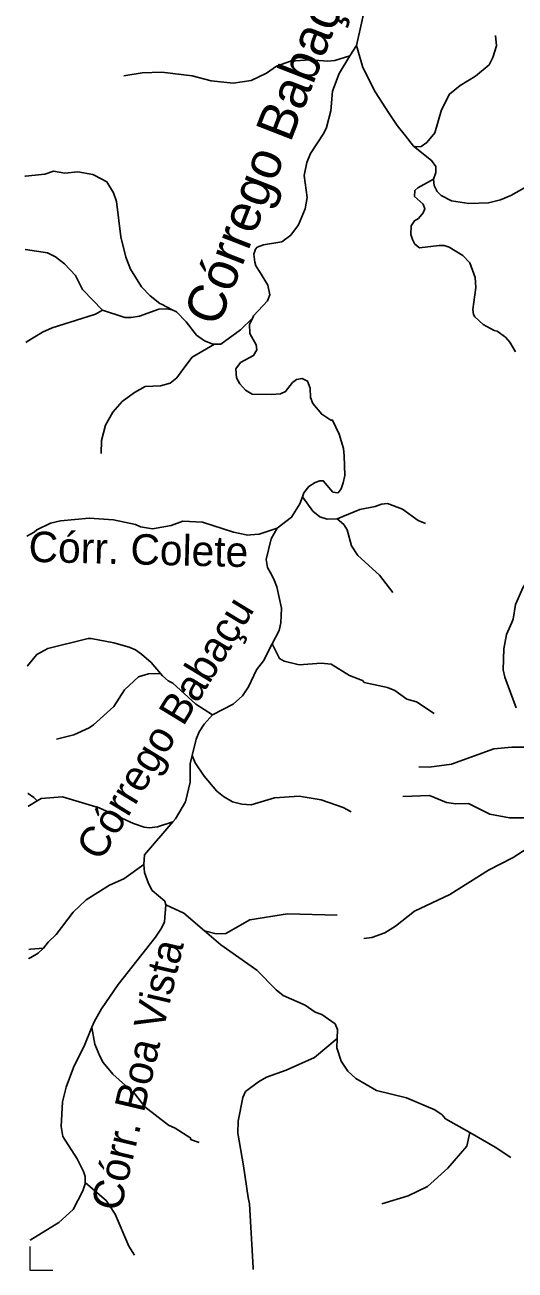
# Model space of a CAD drawing. Extents: x 393 to 446.6, y 8175.5 to 8231.
# Drawn here: x 393.24 to 395.81, y 8175.47 to 8182.01 of the extents above; entities that cross this region are included whole.
import ezdxf
from ezdxf.enums import TextEntityAlignment as Align

# ---------------------------------------------------------------- set-up
doc = ezdxf.new("R2010")
doc.units = 0
doc.header["$LTSCALE"] = 0.064
doc.linetypes.add('LONG_DASHED', pattern=[7.5, 6, -1.5])
doc.layers.add('61', color=7, linetype='Continuous')
for name, color, linetype, lineweight in [('63', 7, 'Continuous', 13), ('7', 7, 'Continuous', 25), ('9', 7, 'LONG_DASHED', 25)]:
    doc.layers.add(name, color=color, linetype=linetype, lineweight=lineweight)

msp = doc.modelspace()

# ---------------------------------------------------------------- linework, layer by layer
at = {"layer": '63'}
msp.add_lwpolyline([(393.2669, 8175.5946), (393.2669, 8175.4714), (393.3883, 8175.4714)], dxfattribs=at)
at = {"layer": '7'}
msp.add_line((394.948, 8181.8527), (394.9815, 8181.9071), dxfattribs=at)
for points in [[(394.9815, 8181.9071), (395.0342, 8182.1402)], [(395.7128, 8181.9584), (395.7172, 8181.9044), (395.6979, 8181.843), (395.6785, 8181.8043), (395.6075, 8181.7445), (395.5267, 8181.696), (395.4702, 8181.6509), (395.4282, 8181.5685), (395.3943, 8181.4474), (395.3523, 8181.3973), (395.3216, 8181.3763), (395.299, 8181.3731), (395.2815, 8181.378)], [(395.2815, 8181.378), (395.2394, 8181.4311), (395.1957, 8181.4861), (395.1537, 8181.5491), (395.081, 8181.6622), (395.0148, 8181.7914), (394.9815, 8181.9071)], [(393.7599, 8181.7473), (393.857, 8181.7623), (393.9604, 8181.7655), (394.1186, 8181.7461), (394.2187, 8181.7203), (394.335, 8181.709), (394.4287, 8181.7219), (394.5094, 8181.7606), (394.5627, 8181.7978), (394.6354, 8181.8236), (394.7387, 8181.8301), (394.831, 8181.8233), (394.8683, 8181.8279), (394.948, 8181.8527)], [(394.4371, 8180.4757), (394.4416, 8180.4849), (394.5142, 8180.5641), (394.5271, 8180.5964), (394.5174, 8180.6464), (394.4762, 8180.7131), (394.4545, 8180.7482), (394.448, 8180.7676), (394.4432, 8180.8095), (394.4528, 8180.8354), (394.461, 8180.8467), (394.4933, 8180.858), (394.5902, 8180.8741), (394.6369, 8180.9096), (394.6773, 8180.9646), (394.7128, 8181.0485), (394.7241, 8181.1067), (394.708, 8181.2229), (394.7209, 8181.2908), (394.7403, 8181.3392), (394.8113, 8181.4458), (394.8243, 8181.4748), (394.8469, 8181.5621), (394.8565, 8181.6654), (394.8905, 8181.7591), (394.948, 8181.8527)], [(396.9003, 8181.7475), (396.9061, 8181.7102), (396.9009, 8181.6686), (396.8427, 8181.5394), (396.8137, 8181.4975), (396.7523, 8181.4409), (396.6377, 8181.3698), (396.5521, 8181.3053), (396.4762, 8181.2827), (396.36, 8181.2681), (396.1791, 8181.2681), (396.1016, 8181.2584), (396.0112, 8181.2326), (395.9078, 8181.1825), (395.8495, 8181.1496), (395.7932, 8181.1179), (395.7383, 8181.0953), (395.6753, 8181.0792), (395.5719, 8181.076), (395.4815, 8181.0905), (395.4266, 8181.1179), (395.4056, 8181.1389), (395.3894, 8181.1713), (395.3864, 8181.2035)], [(395.3864, 8181.2035), (395.3991, 8181.2391), (395.3991, 8181.2698), (395.3765, 8181.3021), (395.2815, 8181.378)], [(395.8174, 8180.2961), (395.7867, 8180.3477), (395.7641, 8180.3736), (395.7205, 8180.4058), (395.7044, 8180.4091), (395.6478, 8180.4397), (395.6042, 8180.4801), (395.5961, 8180.4931), (395.5929, 8180.5189), (395.609, 8180.6352), (395.6058, 8180.6868), (395.5767, 8180.7643), (395.5412, 8180.8031), (395.4686, 8180.8467), (395.4428, 8180.8547), (395.4169, 8180.8547), (395.3136, 8180.8434), (395.2893, 8180.8628), (395.2764, 8180.8871), (395.2683, 8180.9129), (395.2699, 8180.9581), (395.2877, 8180.9856), (395.3071, 8180.9968), (395.3329, 8181.0275), (395.341, 8181.0485), (395.3329, 8181.0728), (395.2877, 8181.1131), (395.2893, 8181.1438), (395.3039, 8181.1583), (395.3864, 8181.2035)], [(394.6986, 8179.5348), (394.7064, 8179.5565), (394.7322, 8179.5888), (394.7645, 8179.6097), (394.7894, 8179.6195), (394.8081, 8179.6194), (394.8582, 8179.5597), (394.8856, 8179.5548), (394.9018, 8179.5759), (394.9115, 8179.6082), (394.9211, 8179.6469), (394.9179, 8179.7503), (394.9147, 8179.789), (394.8921, 8179.8633), (394.8566, 8179.9375), (394.8469, 8179.9375), (394.8, 8179.9682), (394.7532, 8180.0248), (394.7403, 8180.0571), (394.7387, 8180.1055), (394.7258, 8180.1426), (394.6967, 8180.1572), (394.6676, 8180.1507), (394.6466, 8180.1362), (394.6095, 8180.0877), (394.5837, 8180.0764), (394.5352, 8180.0716), (394.4351, 8180.0748), (394.3996, 8180.0958), (394.3689, 8180.1281), (394.3527, 8180.1604), (394.3495, 8180.2072), (394.3737, 8180.2412), (394.4416, 8180.2766), (394.4593, 8180.3073), (394.4561, 8180.3332), (394.4222, 8180.3929), (394.4201, 8180.4411), (394.4371, 8180.4757)], [(395.82, 8178.4259), (395.7608, 8178.5876), (395.7528, 8178.6264), (395.756, 8178.7362), (395.7705, 8178.812), (395.7971, 8178.8741), (395.8044, 8178.8912), (395.8174, 8178.9687), (395.8577, 8179.0591), (395.8981, 8179.1173), (395.9449, 8179.1657), (395.9869, 8179.2529), (396.0402, 8179.3191), (396.0596, 8179.3595), (396.0725, 8179.4111), (396.0693, 8179.4596), (396.0031, 8179.6534), (396.0106, 8179.8498)], [(394.5662, 8179.3694), (394.6418, 8179.4273), (394.6854, 8179.4983), (394.6986, 8179.5348)], [(394.88, 8179.4192), (394.8291, 8179.4176), (394.7904, 8179.4289), (394.7532, 8179.4596), (394.699, 8179.5342), (394.6986, 8179.5348)], [(395.3448, 8179.3938), (395.3055, 8179.4111), (395.2231, 8179.4693), (395.1456, 8179.4999), (395.1133, 8179.4967), (395.081, 8179.4838), (395.0003, 8179.4676), (394.88, 8179.4192)], [(395.1738, 8179.0319), (395.1037, 8179.1237), (394.989, 8179.227), (394.9567, 8179.2771), (394.9341, 8179.3611), (394.9163, 8179.3885), (394.88, 8179.4192)], [(394.5395, 8178.7616), (394.5756, 8178.8331), (394.5853, 8178.8718), (394.5885, 8178.9493), (394.5643, 8179.0624), (394.551, 8179.0936), (394.5368, 8179.1269), (394.5142, 8179.1641), (394.5078, 8179.2045), (394.5336, 8179.3143), (394.5662, 8179.3694)], [(393.2538, 8178.6461), (393.2541, 8178.6463), (393.3031, 8178.7055), (393.3612, 8178.7377), (393.5728, 8178.7894), (393.589, 8178.791), (393.7085, 8178.7668), (393.7892, 8178.7442), (393.8215, 8178.7313), (393.8538, 8178.7071), (393.9038, 8178.6635), (393.9524, 8178.6071)], [(394.2267, 8178.3897), (394.335, 8178.4455), (394.3834, 8178.4891), (394.4157, 8178.5359), (394.4577, 8178.6264), (394.4948, 8178.6732), (394.5395, 8178.7616)], [(395.3898, 8178.3966), (395.2974, 8178.4568), (395.2458, 8178.4713), (395.1828, 8178.5165), (395.1456, 8178.5327), (395.0229, 8178.5585), (395.0132, 8178.5698), (394.9454, 8178.5956), (394.8501, 8178.6554), (394.7968, 8178.6603), (394.6806, 8178.6522), (394.6031, 8178.6715), (394.5788, 8178.6845), (394.5395, 8178.7616)], [(393.4067, 8178.2617), (393.4985, 8178.284), (393.5793, 8178.3211), (393.6019, 8178.3373), (393.7084, 8178.4326), (393.7649, 8178.5198), (393.8377, 8178.5892), (393.8893, 8178.6037), (393.9507, 8178.607), (393.9524, 8178.6071)], [(393.9524, 8178.6071), (393.9636, 8178.5941), (393.9926, 8178.5682), (394.0185, 8178.5553), (394.138, 8178.4455), (394.2267, 8178.3897)], [(394.1191, 8178.1751), (394.1396, 8178.2614), (394.1557, 8178.3002), (394.1816, 8178.3405), (394.2267, 8178.3897)], [(395.3098, 8178.1161), (395.3645, 8178.1149), (395.4815, 8178.1306), (395.7027, 8178.2097), (395.798, 8178.2194), (395.8788, 8178.2194), (395.9304, 8178.2275), (396.0338, 8178.2275), (396.0984, 8178.2145), (396.1759, 8178.2145), (396.2227, 8178.221), (396.2517, 8178.242), (396.3052, 8178.2611)], [(394.0179, 8177.8274), (394.0314, 8177.8432), (394.0847, 8177.932), (394.1089, 8178.0353), (394.1089, 8178.1322), (394.1191, 8178.1751)], [(394.9541, 8177.8802), (394.9115, 8177.9029), (394.7968, 8177.9417), (394.6806, 8177.961), (394.5514, 8177.9529), (394.4287, 8177.9158), (394.3802, 8177.919), (394.3318, 8177.932), (394.2833, 8177.9594), (394.2494, 8177.9885), (394.1832, 8178.0676), (394.1347, 8178.1371), (394.1191, 8178.1751)], [(393.2572, 8177.9751), (393.2574, 8177.975), (393.2878, 8177.9553), (393.3063, 8177.937)], [(395.2251, 8177.9607), (395.3653, 8177.9659), (395.4557, 8177.9287), (395.5041, 8177.9223), (395.5703, 8177.9239), (395.6818, 8177.8674), (395.7851, 8177.848), (395.8594, 8177.848), (395.9886, 8177.8609), (396.1406, 8177.8996)], [(393.2575, 8177.9085), (393.2577, 8177.9086), (393.2656, 8177.9132), (393.3063, 8177.937)], [(393.3063, 8177.937), (393.3273, 8177.9493), (393.4388, 8177.9578), (393.631, 8177.8997), (393.8118, 8177.8183), (393.8677, 8177.7997), (393.8957, 8177.7956), (393.9365, 8177.8014), (394.0179, 8177.8274)], [(395.0202, 8177.2137), (395.0621, 8177.2184), (395.1311, 8177.2441), (395.1876, 8177.278), (395.2877, 8177.3571), (395.4718, 8177.4459), (395.6753, 8177.5735), (395.8045, 8177.6397), (395.9223, 8177.7156), (396.0903, 8177.8464), (396.1406, 8177.8996)], [(393.8649, 8177.6019), (393.8699, 8177.6542), (394.0179, 8177.8274)], [(393.3381, 8177.1623), (393.3625, 8177.1949), (393.4049, 8177.2344), (393.4937, 8177.3523), (393.5631, 8177.4168), (393.6859, 8177.4943), (393.7601, 8177.5266), (393.8649, 8177.6019)], [(393.9809, 8177.3907), (393.9751, 8177.4093), (393.9087, 8177.4669), (393.8893, 8177.5025), (393.8683, 8177.5606), (393.8649, 8177.6019)], [(393.5932, 8176.7478), (393.6062, 8176.7791), (393.6438, 8176.8436), (393.731, 8176.9728), (393.9264, 8177.2215), (393.9587, 8177.2683), (393.9733, 8177.3022), (393.9809, 8177.3907)], [(393.2612, 8177.1566), (393.2614, 8177.1566), (393.2712, 8177.1573), (393.3381, 8177.1623)], [(393.2615, 8177.1078), (393.2616, 8177.1079), (393.2729, 8177.1146), (393.3101, 8177.1367), (393.3381, 8177.1623)], [(393.5581, 8175.9319), (393.557, 8175.9628), (393.5489, 8175.9896), (393.5163, 8176.0556), (393.4404, 8176.1734), (393.4323, 8176.2268), (393.4388, 8176.356), (393.4581, 8176.4335), (393.4969, 8176.5368), (393.555, 8176.6563), (393.5932, 8176.7478)], [(394.1568, 8176.1421), (394.1114, 8176.1584), (394.1121, 8176.1638), (394.0298, 8176.2171), (393.9943, 8176.2332), (393.8715, 8176.3285), (393.8182, 8176.3979), (393.702, 8176.5013), (393.6519, 8176.5626), (393.6342, 8176.5949), (393.6091, 8176.6594), (393.5934, 8176.7465), (393.5932, 8176.7478)], [(393.2688, 8175.6294), (393.2688, 8175.6295), (393.4194, 8175.7213), (393.4937, 8175.7891), (393.5453, 8175.8877), (393.5583, 8175.9248), (393.5581, 8175.9319)], [(393.8165, 8175.5493), (393.786, 8175.597), (393.7149, 8175.7649), (393.6858, 8175.8101), (393.6676, 8175.8365), (393.5593, 8175.9308), (393.5581, 8175.9319)]]:
    msp.add_lwpolyline(points, dxfattribs=at)
at = {"layer": '9'}
for points in [[(393.2412, 8181.2202), (393.2415, 8181.2202), (393.2435, 8181.2204), (393.3451, 8181.2294), (393.392, 8181.2455), (393.4501, 8181.2358), (393.5195, 8181.2423), (393.5986, 8181.2277), (393.6088, 8181.2223), (393.6713, 8181.189), (393.7068, 8181.1325), (393.7214, 8181.0873), (393.744, 8180.9016), (393.7714, 8180.7934), (393.7957, 8180.7304), (393.8538, 8180.6384), (393.899, 8180.5915), (393.9491, 8180.5512), (393.9577, 8180.5467), (394.0147, 8180.5169)], [(393.2431, 8180.8341), (393.2434, 8180.834), (393.2448, 8180.8338), (393.3598, 8180.8169), (393.4017, 8180.795), (393.4485, 8180.7595), (393.5066, 8180.6981), (393.5438, 8180.6238), (393.5456, 8180.622), (393.6492, 8180.5152)], [(393.2454, 8180.3454), (393.2458, 8180.3456), (393.2533, 8180.3502), (393.3338, 8180.3994), (393.3839, 8180.422), (393.5736, 8180.4825), (393.6116, 8180.4946), (393.6492, 8180.5152)], [(393.6492, 8180.5152), (393.761, 8180.4787), (393.7666, 8180.4769), (393.7989, 8180.4769), (393.8425, 8180.4834), (393.9442, 8180.5205), (393.9843, 8180.5227), (394.0147, 8180.5169)], [(394.0147, 8180.5169), (394.0369, 8180.5064), (394.0882, 8180.4539), (394.1413, 8180.3833), (394.1845, 8180.3542), (394.2242, 8180.3378), (394.2391, 8180.3376)], [(394.2391, 8180.3376), (394.2691, 8180.3372), (394.373, 8180.4119), (394.4371, 8180.4757)], [(393.6421, 8179.7617), (393.6439, 8179.831), (393.6648, 8179.9117), (393.702, 8179.9796), (393.7521, 8180.036), (393.8166, 8180.0829), (393.8732, 8180.1152), (393.9539, 8180.1184), (394.004, 8180.1313), (394.0384, 8180.1599), (394.0707, 8180.2034), (394.119, 8180.2684), (394.2365, 8180.3361), (394.2391, 8180.3376)], [(393.2505, 8179.3275), (393.2508, 8179.3277), (393.2902, 8179.3481), (393.3031, 8179.3611), (393.3758, 8179.3966), (393.4275, 8179.4079), (393.5793, 8179.4224), (393.7068, 8179.4143), (393.8215, 8179.3885), (393.8473, 8179.3772), (393.9119, 8179.3659), (394.0088, 8179.3837), (394.0702, 8179.4063), (394.1735, 8179.4014), (394.3366, 8179.3498), (394.4125, 8179.3336), (394.4255, 8179.3347), (394.4707, 8179.3384), (394.5662, 8179.3694)], [(394.1833, 8177.2544), (394.0755, 8177.3467), (393.9809, 8177.3907)], [(394.8809, 8177.3364), (394.6192, 8177.3442), (394.4222, 8177.3119), (394.2963, 8177.2408), (394.2446, 8177.2392), (394.1833, 8177.2544)], [(394.881, 8176.6891), (394.8824, 8176.735), (394.8698, 8176.7651), (394.801, 8176.8149), (394.7646, 8176.8275), (394.7136, 8176.8633), (394.5968, 8176.9145), (394.5597, 8176.9449), (394.4597, 8177.0482), (394.2693, 8177.1807), (394.1833, 8177.2544)], [(394.4403, 8175.4753), (394.4401, 8175.4831), (394.4206, 8175.8198), (394.4141, 8175.8537), (394.3883, 8176.0201), (394.3592, 8176.1912), (394.3608, 8176.2542), (394.385, 8176.3786), (394.3996, 8176.4092), (394.4674, 8176.4609), (394.5094, 8176.4851), (394.6128, 8176.5222), (394.7613, 8176.5884), (394.881, 8176.6891)], [(395.577, 8176.1937), (395.4502, 8176.2666), (395.433, 8176.2864), (395.3937, 8176.3132), (395.2451, 8176.3768), (395.0878, 8176.4149), (394.9793, 8176.4786), (394.9367, 8176.517), (394.9015, 8176.5684), (394.8795, 8176.6393), (394.881, 8176.6891)], [(395.1145, 8175.8194), (395.2538, 8175.8618), (395.3556, 8175.9102), (395.4621, 8176.0071), (395.5622, 8176.1234), (395.577, 8176.1937)], [(395.7921, 8176.0625), (395.7102, 8176.1172), (395.577, 8176.1937)]]:
    msp.add_lwpolyline(points, dxfattribs=at)

# ---------------------------------------------------------------- texts
at = {"layer": '61'}
for s, height, rotation, p in [('Córrego Babaçu', 0.2, 68.711, (394.6104, 8181.3294)), ('Córr. Colete', 0.16, 358.603, (393.8356, 8179.1792)), ('Córrego Babaçu', 0.16, 58.627, (394.0445, 8178.2787)), ('Córr. Boa Vista', 0.16, 76.691, (393.9095, 8176.4798))]:
    msp.add_text(s, height=height, rotation=rotation, dxfattribs=at).set_placement(p, align=Align.CENTER)

doc.saveas('drawing.dxf')
